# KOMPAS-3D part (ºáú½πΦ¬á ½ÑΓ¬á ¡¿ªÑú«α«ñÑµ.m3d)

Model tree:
1. Эскиз:1
2. Операция выдавливания:1
     Расстояние 1 = 1
3. Эскиз:2
4. Операция выдавливания:2
     Расстояние 1 = 12
5. Скругление:4
     Радиус = 0.5
6. Эскиз:3
7. Операция выдавливания:3
     Расстояние 1 = 20
8. Скругление:5
     Радиус = 0.5
9. Скругление:6
     Радиус = 0.5
10. Эскиз:4
11. Операция выдавливания:4
     Расстояние 1 = 8; Расстояние 2 = 1
12. Скругление:8
     Радиус = 0.5
